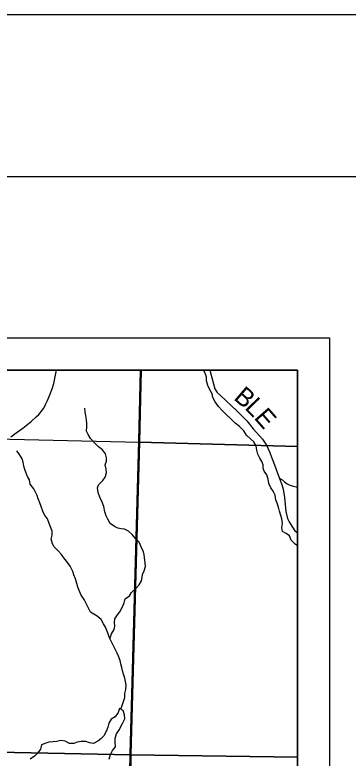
# Model space of a CAD drawing. Extents: x -1.2 to 34, y -8.5 to 22.
# Drawn here: x 8.026 to 9.057, y 19.699 to 22 of the extents above; entities that cross this region are included whole.
import ezdxf

# ---------------------------------------------------------------- set-up
doc = ezdxf.new("R2010")
doc.units = 0
for name, color, linetype in [('GM_X_County_Road', 7, 'Continuous'), ('GM_X_County_Road_Text', 7, 'Continuous'), ('GM_X_Major_Lake', 7, 'Continuous'), ('GM_X_Minor_River', 7, 'Continuous'), ('GM_X_Section', 7, 'Continuous'), ('GM_X_Township_Road', 7, 'Continuous'), ('GM_X_Unincorporated_Text', 7, 'Continuous'), ('SH_Border', 7, 'Continuous'), ('SH_Cut_Line', 7, 'Continuous'), ('SH_Data', 7, 'Continuous')]:
    doc.layers.add(name, color=color, linetype=linetype)

msp = doc.modelspace()

# ---------------------------------------------------------------- linework, layer by layer
at = {"layer": 'GM_X_County_Road'}
for points in [[(8.0135, 20.6936), (8.0296, 20.7065), (8.0499, 20.7206), (8.0756, 20.7409), (8.0917, 20.7552), (8.0993, 20.7625), (8.1043, 20.7682), (8.1082, 20.7729), (8.115, 20.7819), (8.1208, 20.7939), (8.1268, 20.8064), (8.1337, 20.8234), (8.1412, 20.8418), (8.1461, 20.8591), (8.1496, 20.8742), (8.1542, 20.9)], [(8.6292, 20.9), (8.6449, 20.8421), (8.6519, 20.8312), (8.6618, 20.8214), (8.7126, 20.774), (8.7431, 20.7432), (8.7632, 20.7187), (8.7919, 20.6859), (8.805, 20.6675), (8.8151, 20.6456), (8.8199, 20.6304), (8.8261, 20.6148), (8.8448, 20.565), (8.8522, 20.5459), (8.856, 20.5312), (8.8606, 20.5053), (8.8641, 20.4627), (8.869, 20.441), (8.8747, 20.4304), (8.8776, 20.425), (8.8921, 20.4026), (8.9, 20.3975)]]:
    msp.add_lwpolyline(points, dxfattribs=at)
at = {"layer": 'GM_X_Major_Lake'}
msp.add_lwpolyline([(8.3172, 19.6953), (8.3211, 19.7102), (8.3282, 19.7224), (8.3367, 19.7343), (8.3365, 19.748), (8.3359, 19.7609), (8.3406, 19.7742), (8.3495, 19.7873), (8.3535, 19.7968), (8.3587, 19.8064), (8.3657, 19.8202), (8.3651, 19.8331), (8.3607, 19.8459), (8.3499, 19.8529), (8.3452, 19.8399), (8.3359, 19.8269), (8.3235, 19.8199), (8.3161, 19.8068), (8.3133, 19.7943), (8.3078, 19.7809), (8.3012, 19.7683), (8.2918, 19.7583), (8.2821, 19.7509), (8.2685, 19.7446), (8.2563, 19.7463), (8.2448, 19.7503), (8.2311, 19.7504), (8.2182, 19.7487), (8.2084, 19.7443), (8.1947, 19.7441), (8.1813, 19.7519), (8.168, 19.7535), (8.1551, 19.7503), (8.1445, 19.7493), (8.1308, 19.748), (8.121, 19.7448), (8.1078, 19.7396), (8.1049, 19.7271), (8.0964, 19.7152), (8.0863, 19.7047), (8.0731, 19.6958)], dxfattribs=at)
at = {"layer": 'GM_X_Minor_River'}
for points in [[(8.9, 20.3565), (8.8934, 20.3617), (8.8811, 20.3741), (8.876, 20.3874), (8.8653, 20.3945), (8.8543, 20.4001), (8.8523, 20.4133), (8.8541, 20.4251), (8.8516, 20.4399), (8.8489, 20.4497), (8.8446, 20.463), (8.8418, 20.4755), (8.8372, 20.4879), (8.8333, 20.4989), (8.8309, 20.5129), (8.8251, 20.5254), (8.8178, 20.5352), (8.8119, 20.5488), (8.8099, 20.5624), (8.8056, 20.5757), (8.7972, 20.587), (8.794, 20.5968), (8.794, 20.6067), (8.7897, 20.6169), (8.7839, 20.6274), (8.7773, 20.6399), (8.7746, 20.6524), (8.7725, 20.6653), (8.7656, 20.6781), (8.7553, 20.6879), (8.743, 20.6988), (8.7342, 20.712), (8.7207, 20.7251), (8.7077, 20.736), (8.6936, 20.7492), (8.6794, 20.7631), (8.6671, 20.7755), (8.656, 20.7879), (8.6456, 20.8019), (8.6379, 20.8151), (8.6359, 20.8272), (8.6285, 20.8412), (8.6228, 20.8525), (8.6184, 20.8669), (8.6184, 20.8779), (8.6148, 20.8904), (8.6093, 20.9)], [(8.3198, 20.0687), (8.3249, 20.0837), (8.3331, 20.097), (8.335, 20.1076), (8.3341, 20.1186), (8.3351, 20.1304), (8.343, 20.1422), (8.3505, 20.1522), (8.358, 20.1655), (8.3636, 20.1796), (8.3665, 20.1918), (8.3801, 20.2017), (8.3861, 20.2117), (8.4008, 20.2251), (8.4106, 20.235), (8.4173, 20.2483), (8.4191, 20.2578), (8.4205, 20.2677), (8.4254, 20.2791), (8.4298, 20.2925), (8.4289, 20.3038), (8.4273, 20.319), (8.4257, 20.3296), (8.4225, 20.3398), (8.4167, 20.353), (8.4098, 20.367), (8.4002, 20.3776), (8.3891, 20.3911), (8.3772, 20.402), (8.365, 20.4076), (8.3547, 20.4086), (8.3444, 20.4108), (8.3341, 20.4161), (8.3208, 20.4258), (8.3134, 20.4383), (8.308, 20.4492), (8.3041, 20.4617), (8.3009, 20.478), (8.2959, 20.4912), (8.2881, 20.5071), (8.2831, 20.5214), (8.2814, 20.5358), (8.2844, 20.5454), (8.2976, 20.558), (8.3054, 20.5687), (8.3087, 20.582), (8.3083, 20.593), (8.3055, 20.6066), (8.3088, 20.6184), (8.3095, 20.6286), (8.3056, 20.6411), (8.2963, 20.6532), (8.2841, 20.6626), (8.2711, 20.6757), (8.2599, 20.6882), (8.2522, 20.701), (8.2476, 20.7108), (8.2478, 20.7248), (8.2485, 20.7343), (8.2476, 20.7472), (8.2456, 20.7597), (8.2429, 20.7696), (8.2416, 20.7821)], [(8.3535, 19.8506), (8.3584, 19.8651), (8.3624, 19.8772), (8.3658, 19.8871), (8.366, 19.8985), (8.3686, 19.9114), (8.3696, 19.9247), (8.368, 19.9365), (8.3656, 19.9467), (8.3613, 19.9588), (8.359, 19.9694), (8.357, 19.9796), (8.3538, 19.9906), (8.3518, 20.0016), (8.3468, 20.0144), (8.3418, 20.0242), (8.3352, 20.0378), (8.3286, 20.0511), (8.3236, 20.0609), (8.3174, 20.0737), (8.3139, 20.0839), (8.31, 20.0945), (8.3057, 20.1047), (8.3003, 20.1149), (8.293, 20.1282), (8.2804, 20.1379), (8.2697, 20.1443), (8.2601, 20.151), (8.2512, 20.1669), (8.2462, 20.1774), (8.24, 20.1895), (8.2312, 20.2035), (8.2246, 20.2178), (8.2207, 20.2281), (8.2176, 20.2398), (8.2133, 20.2538), (8.2082, 20.2659), (8.2047, 20.2768), (8.197, 20.2931), (8.185, 20.3082), (8.177, 20.3187), (8.1697, 20.3289), (8.1582, 20.3413), (8.147, 20.3526), (8.142, 20.3628), (8.1381, 20.3772), (8.141, 20.389), (8.1409, 20.4011), (8.1362, 20.4151), (8.1312, 20.4253), (8.1262, 20.4397), (8.1177, 20.4521), (8.1119, 20.4638), (8.1068, 20.4778), (8.1033, 20.4888), (8.0979, 20.502), (8.0944, 20.5122), (8.0897, 20.5228), (8.0843, 20.533), (8.0728, 20.5466), (8.0704, 20.5606), (8.0646, 20.5708), (8.0603, 20.5814), (8.056, 20.5927), (8.0533, 20.6033), (8.0513, 20.6154), (8.0485, 20.6253), (8.0401, 20.6388), (8.0312, 20.6505)]]:
    msp.add_lwpolyline(points, dxfattribs=at)
at = {"layer": 'GM_X_Section'}
for points in [[(8.4165, 20.9), (7.3889, 20.9), (7.3857, 20.701), (8.4117, 20.6773)], [(8.9, 20.6636), (8.9, 20.9), (8.4165, 20.9), (8.4117, 20.6773)], [(7.3857, 20.701), (8.4117, 20.6773), (8.3845, 19.7092), (7.3559, 19.7295)], [(8.9, 19.7023), (8.9, 20.6636), (8.4117, 20.6773), (8.3845, 19.7092)], [(8.3845, 19.7092), (8.3694, 18.7126), (7.3389, 18.7336), (7.3559, 19.7295)], [(8.9, 18.7005), (8.9, 19.7023), (8.3845, 19.7092), (8.3694, 18.7126)]]:
    msp.add_lwpolyline(points, close=True, dxfattribs=at)
at = {"layer": 'GM_X_Township_Road'}
msp.add_lwpolyline([(8.8448, 20.565), (8.8508, 20.5627), (8.8607, 20.5543), (8.8689, 20.5477), (8.8748, 20.5451), (8.8843, 20.5415), (8.9, 20.5382)], dxfattribs=at)
at = {"layer": 'GM_X_Unincorporated_Text'}
msp.add_lwpolyline([(6.665, 17.7216), (6.6751, 17.7216), (6.7322, 17.7204), (7.1254, 17.7122), (7.3722, 17.707), (7.8111, 17.6977), (7.9782, 17.6941), (8.3326, 17.6871), (8.3461, 18.0704), (8.364, 18.7117), (8.3686, 18.968), (8.382, 19.7108), (8.4089, 20.6815), (8.4143, 20.9), (2.465, 20.9)], dxfattribs=at)
msp.add_lwpolyline([(8.9, 17.6758), (8.9, 20.9), (8.4143, 20.9), (8.4089, 20.6815), (8.382, 19.7108), (8.3686, 18.968), (8.364, 18.7117), (8.3461, 18.0704), (8.3326, 17.6871)], close=True, dxfattribs=at)
at = {"layer": 'SH_Border'}
msp.add_lwpolyline([(1.5, 21.5), (33.5, 21.5), (33.5, 0.5), (1.5, 0.5)], close=True, dxfattribs=at)
at = {"layer": 'SH_Cut_Line'}
msp.add_lwpolyline([(0, 0), (34, 0), (34, 22), (0, 22)], close=True, dxfattribs=at)
msp.add_lwpolyline([(6.665, 17.7216), (6.6751, 17.7216), (6.7322, 17.7204), (7.1254, 17.7122), (7.3722, 17.707), (7.8111, 17.6977), (7.9782, 17.6941), (8.3326, 17.6871), (8.9, 17.6758), (8.9, 20.9), (2.465, 20.9)], dxfattribs=at)
at = {"layer": 'SH_Data'}
for p, q in [((2, 21), (9, 21)), ((9, 21), (9, 14)), ((9, 21), (9, 14)), ((2.1, 20.9), (8.9, 20.9)), ((8.9, 20.9), (8.9, 14.1)), ((8.9, 20.9), (8.9, 14.1))]:
    msp.add_line(p, q, dxfattribs=at)

# ---------------------------------------------------------------- texts
at = {"layer": 'GM_X_County_Road_Text'}
for s, rotation, p in [('B', 319.314, (8.7002, 20.8112)), ('L', 314.25, (8.7346, 20.7817)), ('E', 311.1577, (8.7637, 20.7518))]:
    msp.add_text(s, height=0.0568, rotation=rotation, dxfattribs=at).set_placement(p)

doc.saveas('drawing.dxf')
